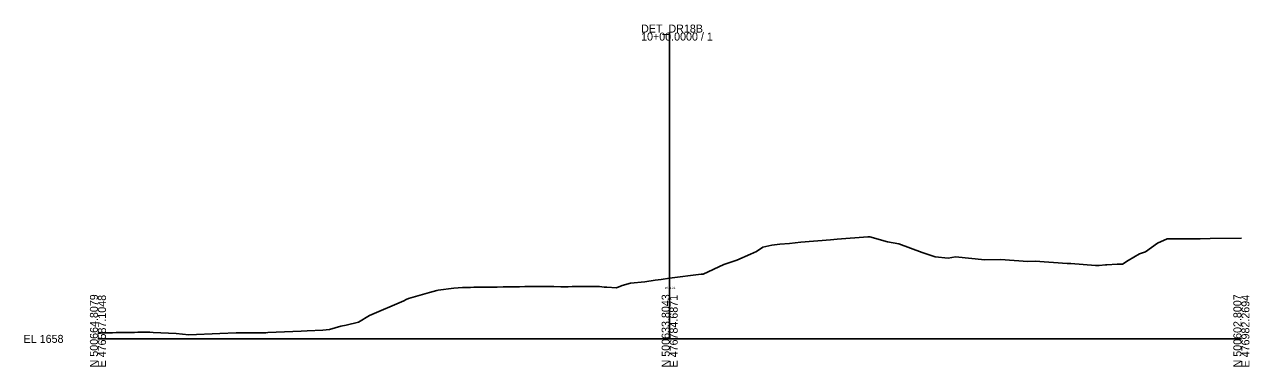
# Model space of a CAD drawing. Extents: x -26 to 403, y -10 to 2570.
# Drawn here: x -25.7 to 402.8, y -9.7 to 110.1 of the extents above; entities that cross this region are included whole.
import ezdxf

# ---------------------------------------------------------------- set-up
doc = ezdxf.new("R2010")
doc.units = 0
for name, color, linetype in [('Exist Cross Section Cell', 7, 'Continuous'), ('Exist XS Center Line Elevation Label', 7, 'Continuous'), ('Exist XS Ground Line', 7, 'Continuous')]:
    doc.layers.add(name, color=color, linetype=linetype)

msp = doc.modelspace()

# ---------------------------------------------------------------- linework, layer by layer
at = {"layer": 'Exist Cross Section Cell'}
for p, q in [((200, 0), (200, 107.3)), ((0, 0), (200, 0)), ((200, 0), (400, 0))]:
    msp.add_line(p, q, dxfattribs=at)
at = {"layer": 'Exist XS Ground Line'}
msp.add_lwpolyline([(0, 2.01), (0.84, 2.05), (1.38, 2.07), (1.88, 2.09), (2.76, 2.12), (3.82, 2.14), (5.04, 2.17), (6.36, 2.19), (7.56, 2.2), (9.39, 2.23), (10.09, 2.24), (10.61, 2.25), (12.8, 2.27), (13.93, 2.29), (15.15, 2.31), (17.62, 2.34), (18.17, 2.35), (19.36, 2.28), (27.4, 1.92), (31.81, 1.46), (42.66, 1.92), (48.33, 2.12), (48.89, 2.14), (49.3, 2.13), (50.19, 2.11), (58.75, 2.16), (59.44, 2.21), (71.07, 2.64), (73.14, 2.77), (78.66, 3.09), (80.98, 3.23), (84.92, 4.42), (86.83, 4.78), (91.14, 5.83), (95.02, 8.2), (107.03, 13.37), (107.86, 13.8), (108.65, 14.13), (116, 16.22), (118.6, 16.99), (119.03, 17.03), (124.54, 17.77), (127.48, 17.98), (128.14, 18.03), (129.39, 18.04), (130.37, 18.05), (131.51, 18.06), (131.91, 18.06), (132.62, 18.07), (134.11, 18.08), (135.45, 18.09), (136.63, 18.11), (138.49, 18.13), (139.19, 18.14), (139.69, 18.15), (141.78, 18.19), (142.27, 18.19), (144.24, 18.22), (146.25, 18.25), (146.77, 18.25), (147.45, 18.26), (149.3, 18.29), (150, 18.3), (151.14, 18.32), (151.85, 18.33), (152.23, 18.33), (152.68, 18.32), (154.35, 18.31), (154.99, 18.31), (156.88, 18.3), (159.06, 18.29), (159.48, 18.29), (161.98, 18.28), (162.57, 18.28), (164.48, 18.28), (165.93, 18.29), (167, 18.29), (168.43, 18.29), (169.68, 18.3), (170.22, 18.3), (171.87, 18.31), (172.74, 18.31), (174.1, 18.32), (174.97, 18.33), (175.51, 18.29), (177.13, 18.17), (178.03, 18.1), (181.39, 17.85), (183.43, 18.7), (186.25, 19.51), (191.29, 20.03), (194.96, 20.59), (197, 20.84), (200, 21.22), (211, 22.63), (211.77, 22.72), (218.93, 26.1), (223.47, 27.53), (228.23, 29.66), (230.39, 30.59), (232.55, 32.15), (235.77, 32.78), (238.58, 33.17), (241.91, 33.42), (245.85, 33.87), (256.23, 34.68), (258.57, 34.96), (269.3, 35.74), (270.02, 35.77), (276.15, 33.96), (280.18, 33.31), (288.37, 30.23), (292.88, 28.78), (297.47, 28.3), (300.01, 28.72), (310.27, 27.65), (315.68, 27.84), (325.25, 27.12), (327.91, 27.25), (339.04, 26.35), (340.33, 26.41), (348.95, 25.73), (350.25, 25.73), (352.51, 25.95), (352.91, 25.97), (356.56, 26.18), (358.37, 26.2), (360.34, 27.41), (364.32, 29.77), (366.46, 30.54), (370.69, 33.56), (374.07, 35.01), (375.01, 35.02), (376.5, 35.01), (378.8, 35.06), (385.64, 35.08), (389.03, 35.13), (400, 35.29)], dxfattribs=at)

# ---------------------------------------------------------------- texts
at = {"layer": 'Exist Cross Section Cell'}
for s, p in [('10+00.0000 / 1', (190, 104.5)), ('DET_DR18B', (190, 107.3)), ('EL 1658', (-26, -1.4))]:
    msp.add_text(s, height=2.8, dxfattribs=at).set_placement(p)
for s, p in [('N 500664.8079', (0, -10)), ('E 476587.1048', (2.8, -10)), ('N 500633.8043', (200, -10)), ('E 476784.6871', (202.8, -10)), ('N 500602.8007', (400, -10)), ('E 476982.2694', (402.8, -10))]:
    msp.add_text(s, height=2.8, rotation=90, dxfattribs=at).set_placement(p)
at = {"layer": 'Exist XS Center Line Elevation Label'}
msp.add_text('1679.22', height=0.75, dxfattribs=at).set_placement((198.24, 17.47))

doc.saveas('drawing.dxf')
